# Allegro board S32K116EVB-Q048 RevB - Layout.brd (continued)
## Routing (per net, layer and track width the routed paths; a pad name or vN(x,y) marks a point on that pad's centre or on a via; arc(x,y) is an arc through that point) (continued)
P3V3: length 33.7
  TOP w0.381: 41.49,32.42 TS5.1 ; TS5.1 43.4,33.5 ; TS5.1 45.3,32.42 ; TS5.1 43.4,31.34
  TOP w0.508: C557.1 v1(44.67,9.56) ; 42.32,30.53 C24.1 44.23,30.53
  TOP w0.635: C557.1 TP510.1 45.55,5.25 J3.7
  TOP w0.762: 39.9,33.91 R737.2 41.43,33.91 ; 42.44,34.54 C548.1 ; C548.1 42.95,34.04 ; C548.1 42.95,35.05 ; J10.1 39.57,30.52 ; J10.1 40.52,29.57 ; J10.1 38.61,29.57 ; J10.1 39.57,29.42 40.54,28.45
  L3_INT_1 w0.508: J10.1 39.57,30.52 ; J10.1 40.3,30.3 ; J10.1 38.83,30.3 ; J10.1 40.3,28.83 ; J10.1 39.57,28.61 ; J10.1 38.61,29.57 ; J10.1 38.83,28.83 ; J10.1 40.52,29.57 ; 44.73,5.12 J3.7 ; J3.7 46.42,5.86 ; J3.7 44.94,5.86 ; J3.7 45.68,6.07 ; J3.7 44.94,4.38
  vias: v1(41.62,27.72) v1(41.74,30.52) v1(41.74,29.12) v1(44.92,30.52) v1(44.92,28.61)
P3V3_SDA: length 33.9
  TOP w0.178: v1(33.64,39.64) 33.64,39.65 U9.5
  TOP w0.203: U1.1 9.04,50.33 ; U1.1 8.46,50.04 ; U1.1 8.46,50.62 ; C18.1 30.44,35.34 ; 30.5,36.03 C19.1 ; C19.1 31.01,35.52 ; C19.1 31.01,36.54 ; 31.02,36.6 R52.1 30.51,37.11 ; R77.1 20.43,28.74 C26.1 ; 9.7,50.55 C3.1 9.19,51.06 ; R607.1 v1(8.72,53.38)
  TOP w0.254: U8.7 16.58,40.88 16.01,40.88 15.64,40.52 ; U10.1 v1(27.41,38.62) ; J12.1 18.73,28.86 18.85,28.74 C26.1 ; v1(27.83,41.93) 27.86,41.93 28.13,41.66 U7.1 ; R1.2 v1(9.42,54.36) ; U8.11 v1(16.65,37.9) ; U4.1 28.54,45.51 v1(28.2,45.85) ; U2.1 v1(27.21,48.5) ; v1(30.04,45.2) 30.3,45.46 R15.1 ; U8.1 v1(19.51,43.09)
  TOP w0.381: R3.1 9.8,51.16 C3.1
  TOP w0.508: R60.1 v1(11.75,37.33) ; R42.1 R39.2 37.61,41.46 C10.1 v1(37.61,42.64) ; R30.1 30.95,42.34 30.92,42.37 30.92,42.95 v1(30.91,42.95) ; R12.1 26.29,45.87 v1(25.42,46.74) ; v1(12.41,39.29) R627.2 13.17,40.17 13.52,40.52 C12.1 15.64,40.52
  TOP w0.635: C6.1 17.76,44.83 C7.1 18.65,43.95 v1(19.51,43.09)
  BOTTOM w0.635: 17.32,28.13 J12.1
  vias: v1(8.85,50.86) v1(30.38,36.71)
P5V0: length 168
  TOP w0.508: C558.1 v1(48.09,7.98) ; R729.2 v1(5.74,56.01)
  TOP w0.584: R95.2 R96.2 R97.2
  TOP w0.635: R95.2 109.18,18.83 106.64,21.37 106.64,25.44 v1(105.5,26.58) ; v1(44.16,14.52) 45.17,13.5 R56.1 ; R624.1 35.78,36.11 34.76,35.09 C22.1 ; C22.1 C550.1 ; C22.1 R169.1 32.65,33.69 32.22,33.26 C21.1 28.46,33.26 TP527.1
  L3_INT_1 w0.381: 47.27,5.12 J3.9 ; J3.9 47.48,4.38 ; J3.9 48.96,5.86 ; J3.9 47.48,5.86 ; J3.9 49.17,5.12 ; J3.9 48.96,4.38 ; J3.9 48.22,6.07
  BOTTOM w0.508: 42.13,32.8 49.39,32.8 56.12,26.07 66.15,26.07 67.48,27.39 70.93,27.39 71.95,26.38 77.36,26.38 78.99,28.02 80.36,28.02 81.32,28.97 103.11,28.97 v1(105.5,26.58) ; v1(5.74,56.01) 5.74,55.63 3.83,53.72 3.83,52.32 2.74,51.23 2.74,49.48 6.37,45.85 6.37,35.64 8.89,33.12 8.89,28.09 10.56,26.42 15.95,26.42 16.91,27.38 18.9,27.38 22.4,30.88 23.87,30.88 J107.2
  BOTTOM w0.635: J10.3 35.44,29.57 ; J10.3 34.49,30.52 ; J10.3 34.49,28.61 ; J10.3 33.53,29.57 ; 24.28,29.51 J107.2 ; J107.2 25.24,30.47 ; J107.2 25.24,28.56 ; J107.2 26.19,29.51 ; 28.41,31.97 TP527.1 ; TP527.1 27.06,33.31 ; TP527.1 29.76,33.31
  vias: v1(40.6,25.74) v1(41.49,25.74) v1(42.48,25.72)
P5V0_SDA_USB_CONN_VBUS: length 5.6
  TOP w0.152: 8.02,40.99 D17.2 7.4,41.45
  TOP w0.356: 5.64,42.72 J7.1
  TOP w0.381: L1.1 8.02,40.99
  TOP w0.635: 5.64,42.72 6.92,41.45 7.4,41.45
P5V_SBC: length 93.7
  TOP w0.203: R620.1 41.75,22.77 ; R620.1 41.24,22.26 ; R620.1 40.73,22.77 ; R619.1 36.92,25.44 ; R619.1 37.43,24.93 ; R619.1 36.41,24.93 ; v1(36.92,19.6) 37.3,19.22 R621.1 U34.1 ; 41.87,22.39 R562.1 ; R562.1 42.89,22.39 ; R562.1 42.38,21.88 ; 37.62,24.68 U26.1 ; 42.89,22.64 43.01,22.52 U32.1 ; U33.1 v1(47.97,22.52) R617.1 ; 42,24.55 R572.1
  TOP w0.305: U19.5 22.77,17.74 C547.1
  TOP w0.381: 42.63,21.12 42.63,19.34 R576.1 v1(42.13,18.08) 41.77,17.73 R622.1
  TOP w0.508: v1(12.53,21.63) 12.53,21.63 11.9,21.63 11.61,21.34 R536.1 ; v1(51.45,21.36) 51.59,21.5 v1(52.12,21.5) 52.54,21.08 R618.1 52.91,20.61 53.41,21.12 TP525.1 53.05,21.8 R571.1 TS8.1 ; v1(20.94,14.16) 21.07,14.16 21.09,14.14 C27.1 21.98,14.69 23.18,15.89 23.18,16.68 22.82,17.03 C547.1
  TOP w0.635: R594.1 R535.1 24.16,21.45 v1(25.36,22.66) 25.36,27.1 J107.1
  L3_INT_1 w0.635: v1(25.36,22.66) 22.83,22.66 18.83,26.66 18.55,26.66 18.54,26.67 14.04,26.67 12.53,25.17 v1(12.53,21.63) 14.08,21.63 14.49,22.03 16.87,22.03 17.46,21.45 17.46,14.87 18.17,14.16 v1(20.94,14.16)
  BOTTOM w0.254: v1(42.13,18.08) 41.61,17.56 37.55,17.56 36.93,18.19 36.93,19.6 v1(36.92,19.6)
  BOTTOM w0.508: 27.78,28.56 J107.1 ; J107.1 26.82,28.56 ; J107.1 28.73,30.47 ; J107.1 28.73,28.56 ; J107.1 28.73,29.51 ; J107.1 27.78,30.47 ; J107.1 26.82,30.47
  vias: v1(34.58,24.56) v1(35.57,25.36) v1(35.65,24.14) v1(40.22,22.64) v1(43.01,21.76)
P5V_SDA: length 8.6
  TOP w0.254: U8.6 16.74,41.43 v1(16.62,41.43)
  TOP w0.381: R14.1 22.56,45.36 v1(22.02,45.89)
  TOP w0.508: C15.1 7.5,37.47 7.18,37.79 v1(7.18,38.88) L1.2 ; R57.1 v1(26.57,37.38) ; R70.1 v1(8.14,31.06) ; U11.1 v1(8.08,31.93) ; C25.1 v1(8.15,29.82) ; C11.1 v1(9.35,38.48)
P5V_SDA_PSW: length 26
  TOP w0.584: U11.6 8.08,34.91 v1(6.95,33.78)
  BOTTOM w0.584: J107.3 19.84,26.66 17.3,26.66 16.16,25.53 10.18,25.53 6.95,28.76 v1(6.95,33.78)
VBATT: length 38.6
  TOP w0.508: 25.23,8.42 C555.1 25.74,7.91 ; 54.89,5.12 J3.15 ; J3.15 56.79,5.12 ; J3.15 55.84,6.07 ; J3.15 55.84,4.17 ; TP522.1 25.87,13.32 ; TP522.1 27.22,11.98 ; TP522.1 25.87,10.63 ; TP522.1 24.52,11.98 ; 55.27,8.29 TP507.1 ; TP507.1 56.41,8.29 ; TP507.1 55.84,8.87 ; TP507.1 55.84,7.72 ; 25.74,10.07 C544.1 25.23,9.56 ; 38.06,4.17 J3.1 ; J3.1 37.11,5.12 ; J3.1 38.06,6.07 ; J3.1 39.01,5.12
  TOP w0.635: R606.2 v1(9.61,18.2)
  TOP w0.762: 28.75,10.73 D9.A ; D9.A 28.75,13.22 ; D9.A 27.86,11.98 ; D9.A 29.64,11.98
  TOP w1.27: J16.1 23.2,9.88 ; J16.1 22.29,7.96 ; J16.1 22.29,11.8
  L3_INT_1 w0.254: 24.52,11.98 TP522.1
  L3_INT_1 w0.635: J11.2 3.84,33.27 ; J11.2 2.82,32.26 ; J11.2 2.82,34.29 ; J11.2 1.81,33.27
  L3_INT_1 w1.27: 21.37,9.88 J16.1 ; J16.1 22.29,11.8 ; J16.1 22.29,7.96 ; J16.1 23.2,9.88
  vias: v2(23.12,6.4) v2(23.93,7.2) v2(24.41,10.41) v2(24.41,8.51) v2(24.92,5.97)
VDD: length 82.1
  TOP w0.254: v1(9.49,45.93) 9.18,45.63 Q10.4
  TOP w0.33: 78.64,45.59 R573.1 ; R573.1 78.64,46.61 ; R573.1 78.13,46.1 ; J15.1 47.12,30.76 ; J15.1 48.07,29.81 ; J15.1 46.16,29.81 ; TS1.1 44.79,43.35 ; TS1.1 44.79,39.53 ; TS1.1 43.71,41.44 ; TS1.1 45.87,41.44 ; C553.1 83.91,41.31 ; C553.1 83.91,40.3 ; C553.1 83.4,40.81 ; 81.99,40.13 R121.1 ; R121.1 82.5,39.62 ; R121.1 83.01,40.13 ; TPAD99.1 47.14,32.77 ; TPAD99.1 46,32.77 ; TPAD99.1 46.57,33.34 ; TPAD99.1 46.57,32.2 ; 51.52,34.01 TP511.1 ; TP511.1 52.1,34.58 ; TP511.1 51.52,35.15 ; TP511.1 50.95,34.58 ; 41.79,36.83 TP9.1 ; TP9.1 43.13,38.18 ; TP9.1 44.48,36.83 ; 47.95,42.8 TP4.1 ; TP4.1 50.65,42.8 ; TP4.1 49.3,41.45 ; TP4.1 49.3,44.15 ; 78.32,48.93 R623.1 78.83,48.42 ; 49.49,34.33 R593.1 50.13,33.57 ; 40.45,38.32 SH1.2 41.13,37.72 ; 78.83,50.46 R574.1 78.32,49.95 ; 47.33,32.04 R117.1 47.97,31.28
  TOP w0.381: R733.1 v1(12.22,46.1)
  TOP w0.508: SW3.2 v1(113.97,27.21) ; v1(45.68,14.92) 45.68,16.29 R604.1 ; SW2.4 v1(113.97,30.97) ; SW3.4 v1(113.97,19.46) ; SW2.2 v1(113.97,38.79)
  TOP w0.635: 83.77,42.63 J14.1 85.1,43.36
  L3_INT_1 w0.508: 41.79,36.83 TP9.1 ; TP9.1 43.13,35.48 ; TP9.1 42.12,35.81 ; TP9.1 42.12,37.85 ; TP9.1 44.15,35.81 ; TP9.1 44.15,37.85 ; TP9.1 43.13,38.18 ; TP9.1 44.48,36.83 ; J10.2 37.76,28.83 ; J10.2 36.07,29.57 ; J10.2 36.29,30.3 ; J10.2 37.76,30.3 ; J10.2 36.29,28.83 ; J10.2 37.03,28.61 ; J10.2 37.03,30.52
  BOTTOM w0.508: v1(45.68,14.92) 45.68,14.67 40.68,9.66 37.93,9.66 34.69,6.42 34.69,3.68 v1(35.98,2.4)
  vias: v1(64.73,1.18) v1(67.27,1.21) v1(69.65,1.18) v1(71.84,1.18) v2(40.86,40.93) v2(40.92,39.5) v2(42.25,39.54) v2(42.38,40.93) v2(43.4,39.54) v2(79.91,55.75) v2(79.91,54.23) v2(79.91,52.7) v2(81.05,55.75) v2(81.05,54.23)
VDD_MCU: length 77.9
  TOP w0.254: 79.68,29.19 U36.31 U37.21 ; U37.3 69.83,29.69 U36.5
  TOP w0.305: U36.5 68.2,29.69 67.99,29.9
  TOP w0.381: 79.68,29.19 80.32,29.19 80.62,29.49 C129.1 81.1,29.49 v1(81.58,29.97) 82.04,30.43 C143.1
  TOP w0.508: 67.99,29.9 66.85,31.04 C140.1 C144.1 66.04,33.2 v1(65.51,33.73)
  TOP w0.584: 50.13,32.04 R117.2 49.49,31.28 ; R300.1 63.84,41.95 ; R300.1 63.84,40.42 ; R300.1 63.21,41.19 ; TS2.1 61.68,38.39 ; TS2.1 59.78,39.47 ; TS2.1 57.87,38.39 ; TS2.1 59.78,37.31 ; 59.46,40.07 D59.1 ; D59.1 58.63,40.89 ; D59.1 60.29,40.89 ; 63.46,42.71 L512.2 ; L512.2 63.97,43.22 ; L512.2 63.97,42.2 ; 47.12,26.31 J15.2 ; J15.2 46.16,27.27 ; J15.2 47.12,28.22 ; J15.2 48.07,27.27
  L3_INT_1 w0.508: v1(64.61,44.23) 64.61,42.83 66.03,41.41 66.03,34.25 v1(65.51,33.73) ; v1(81.58,29.97) 81.58,33.32 83.02,34.76 v1(83.02,36.23) 83.02,38.03 81.38,39.67 81.38,41.68 v1(81.33,41.73)
  BOTTOM w0.508: v1(81.33,41.73) 80.53,40.93 71.66,40.93 70.36,42.24 67.21,42.24 65.21,44.23 v1(64.61,44.23) 64.58,44.26 v1(63.44,44.26)
VDD_PERH: length 188.1
  TOP w0.203: v1(48.86,24.17) 49.03,24.17 49.47,23.73 U33.8 ; U32.8 43.88,23.69 v1(43.41,24.17) ; U34.8 38.8,20 38.7,20.1 38.44,20.1 38.27,19.93 v1(38.27,19.85) ; U26.8 38.55,25.97 38.32,26.2 v1(37.55,26.2) ; R612.1 43.01,26.45 v1(43.27,26.71) R616.1
  TOP w0.381: R615.1 v1(37.44,21.63) ; R614.1 41.65,21.63 v1(41.93,21.35)
  TOP w0.508: R611.1 51.9,26.48 51.55,26.84 49.51,26.84 47.84,25.17 R610.1 ; R610.1 47.25,24.93 46.9,25.28 R609.1 ; R610.1 47.84,24.55 48.22,24.17 v1(48.86,24.17) ; R674.1 v1(105.37,52.54)
  TOP w0.635: v1(34.76,22.9) 34.25,22.39 R538.1 R530.1 R570.1 35.08,26.96 TP541.1 35.84,27.22 R613.1 36.41,26.45 36.66,26.2 v1(37.55,26.2) ; 53.56,12.8 TS6.1 ; TS6.1 51.65,13.88 ; TS6.1 53.56,14.96 ; TS6.1 55.46,13.88 ; TP526.1 48.09,36.77 v1(48.09,34.71) 48.09,33.97 47.97,33.85 R593.2 ; v1(31.93,51.64) 31.47,51.18 30.12,51.18
  TOP w0.762: C554.1 v2(33.74,7.58) 33.74,7.66 C556.1 35.6,8.55 36.28,7.86 39.01,7.86 39.77,7.1 39.77,5.95 J3.3
  L3_INT_1 w0.635: v1(48.86,24.17) 48.59,24.43 48.59,34.21 v1(48.09,34.71) 46.58,36.22 46.58,41.88 38.4,50.06 35.81,50.06 34.77,51.1 32.46,51.1 32.24,51.32 32.24,51.32 v1(31.93,51.64) ; v2(33.74,7.58) 36.41,10.25 36.41,14.41 35.37,15.46 34.38,15.46 32.98,16.85 32.98,21.5 34.38,22.9 v1(34.76,22.9) ; v1(55.33,20.99) 54.67,20.33 54.67,16.19 v1(55.84,15.02) v1(55.84,14.01) v1(55.84,12.99) 55.84,8.9 58.01,6.73 67.64,6.73 68.49,7.58 82.41,7.58 83.4,6.59 v2(83.4,5.25) v2(83.4,4.36)
  BOTTOM w0.508: 39.2,20.99 38.82,21.37 37.69,21.37 v1(37.44,21.63) 36.17,22.9 v1(34.76,22.9) ; 39.2,20.99 39.2,20.1 38.95,19.85 v1(38.27,19.85) ; 39.2,20.99 39.56,21.35 41.93,21.35 v1(41.93,21.35) ; v1(43.41,24.17) 43.41,26.57 v1(43.27,26.71)
  BOTTOM w0.635: v1(55.33,20.99) 52.16,24.17 v1(48.86,24.17) v1(43.41,24.17) 42.25,24.17
  BOTTOM w0.762: v1(37.55,26.2) 38.98,24.78 41.47,24.78 42.08,24.17 42.25,24.17
VDDA_MCU: length 64.1
  TOP w0.254: U36.6 66.9,29.19 66.63,29.46 66.43,29.46
  TOP w0.381: 66.43,29.46 C543.1 66.06,29.79 65.68,30.17 62.15,30.17 C542.1 61.82,29.29 v1(61.24,28.7)
  TOP w0.508: C543.1 65.98,29.38 v1(65.98,28.73) ; R569.1 TP545.1 v1(53.24,37.72)
  TOP w0.584: R300.2 65.37,41.95 ; R300.2 65.37,40.42 ; R300.2 66,41.19 ; 64.99,42.2 L512.1 ; L512.1 64.99,43.22 ; L512.1 65.49,42.71 ; 66.57,41.19 D60.1 ; D60.1 67.4,40.36 ; D60.1 68.22,41.19
  L3_INT_1 w0.508: v1(53.24,37.72) 53.49,37.46 v1(53.49,32) ; v1(60.6,41.91) 59.84,41.15 59.84,30.1 v1(61.24,28.7)
  BOTTOM w0.508: v1(53.49,32) 54.13,31.37 60.09,31.37 62.73,28.73 v1(65.98,28.73) ; v1(70.93,40.02) 69.08,40.02 v1(68.92,40.17) 62.34,40.17 v1(60.6,41.91)
ADC_POT: length 66.8
  TOP w0.16: C549.1 R597.2 TP528.1 105.24,48.2 v1(105.45,47.99) ; v1(84.86,32.51) 85.48,33.14 85.48,38.22 87.53,40.26 v1(87.53,41.27) ; v1(84.48,27.3) 84.5,27.3 84.5,27.28 84.84,27.28 85,27.12 85,26.86 R750.1 ; R711.2 80.29,39.88 v1(79.93,40.23) 79.7,40.23 79.18,40.75 R670.1 ; R727.1 v1(83.15,19.37)
  L3_INT_1 w0.165: v1(84.86,32.51) 83.84,32.51 83.08,31.75 83.08,29.82 82.83,29.57 82.83,28.96 v1(84.48,27.3) 84.5,27.3 84.5,27.28 84.48,27.28 82.61,25.41 82.61,19.9 v1(83.15,19.37)
  BOTTOM w0.16: v1(105.45,47.99) 105.03,48.41 89.2,48.41 88.29,47.5 88.29,42.03 v1(87.53,41.27) 84.84,41.27 83.81,40.23 v1(79.93,40.23)
AREF: length 27.8
  TOP w0.508: R569.2 v1(52.35,41.34)
  L3_INT_1 w0.508: v1(52.35,41.34) 52.41,41.34 53.11,42.04 53.11,45.72 50.19,48.64 42.06,48.64 39.14,51.56 36.45,51.56 34.63,53.38 J2.8
BTN0: length 31.2
  TOP w0.16: R659.2 v1(84.92,34.58) ; C16.1 109.47,31.03 R596.2 TP530.1 106.9,29.32 106.31,28.74 92.54,28.74 91.78,29.5 v1(91.78,31.41)
  BOTTOM w0.16: v1(84.92,34.58) 88.1,31.41 v1(91.78,31.41)
BTN1: length 46.9
  TOP w0.16: R660.2 v1(73.39,16.22) ; C28.1 109.55,27.34 R595.2 TP529.1 106.01,28.11 89.5,28.11 88.31,26.92 88.31,19.96 86.8,18.45 v1(84.17,18.45)
  BOTTOM w0.16: v1(84.17,18.45) 82.26,18.45 81.37,17.56 76.29,17.56 74.94,16.22 v1(73.39,16.22)
CAN_HI: length 22.8
  TOP w0.16: v1(14.44,16.36) 14.82,16.74 U19.18 ; R92.1 2.87,23.28 J13.1 ; R92.1 v1(8.85,23.28) ; R92.1 TP504.1
  L3_INT_1 w0.165: v1(8.85,23.28) 8.85,22.33 10.39,20.79 15.26,20.79 15.58,20.48 15.58,20 14.44,18.86 14.44,18.44 14.43,18.43 14.43,18.05 14.44,18.04 v1(14.44,16.36)
CAN_LO: length 21.2
  TOP w0.16: J13.2 4.53,18.98 4.53,15.02 6.18,13.37 R98.2 7.33,14.26 10.31,17.24 TP503.1 U19.17
EXTAL: length 6.6
  TOP w0.16: Y3.1 57.23,28.25 57.8,28.82 C126.1 59.17,28.82 R91.1 R88.1
JTAG_TCLK/SWD_CLK: length 102.5
  TOP w0.127: U37.30 73.28,31.63 72.92,31.99 72.74,31.99 72.52,32.22 72.42,32.22 72.41,32.24
  TOP w0.16: R626.1 v1(28.03,35.09) ; v1(80.34,43.18) 79.93,43.18 79.78,43.33 R575.1 80.97,43.97 81.63,44.63 J14.4 ; 72.41,32.24 72.28,32.36 U36.46 72.28,34.75 71.38,35.65 71.38,37.93 73.55,40.1 73.55,46.06 72.96,46.65 TP536.1 68.24,48.73 61.73,48.73 60.67,47.66 v1(60.67,44.23)
  L3_INT_1 w0.165: v1(51.08,39.62) 51.08,36.96 v1(50.95,36.83)
  BOTTOM w0.16: v1(51.08,39.62) 51.54,39.17 54.44,39.17 59.51,44.23 v1(60.67,44.23) 60.68,44.22 62.53,44.22 63.08,44.77 65.7,44.77 67.26,43.21 70.51,43.21 71.12,42.6 75.46,42.6 76.27,41.78 79.82,41.78 80.34,42.3 v1(80.34,43.18) ; v1(50.95,36.83) 50.32,36.83 49.68,36.2 46.23,36.2 43.65,38.77 38.67,38.77 36.13,36.23 34.25,36.23 33.11,35.09 v1(28.03,35.09)
JTAG_TDI: length 15
  TOP w0.16: R120.2 v1(78.1,47.73) ; v1(75.06,47.8) 75.06,47.47 73.99,46.41 73.99,45.57 74.26,45.3 TP538.1 74.26,43.26 73.92,42.93 73.92,39.63 R632.1
  BOTTOM w0.16: v1(75.06,47.8) 75.23,47.97 77.86,47.97 v1(78.1,47.73)
JTAG_TDO: length 15.3
  TOP w0.16: v1(80.21,45.59) 79.65,45.04 R119.2 ; R645.1 73.65,38.49 74.26,39.09 74.26,42.58 74.85,43.18 74.85,46.18 v1(74.76,46.27)
  BOTTOM w0.16: v1(80.21,45.59) 75.44,45.59 v1(74.76,46.27)
JTAG_TMS/SWD_DIO: length 73.9
  TOP w0.16: U37.32 72.28,31.59 72.12,31.75 71.42,31.75 71.28,31.89 U36.48 71.28,34.19 70.69,34.78 70.69,38.56 72.86,40.73 72.86,44.49 TP535.1 72.07,44.74 v1(71.64,44.31) ; R625.1 34.69,46.59 v1(34.94,46.34) ; v1(78.76,42.93) 79.26,42.43 80.43,42.43 81.35,43.36 J14.2 R121.2
  BOTTOM w0.16: v1(34.94,46.34) 35.37,45.91 40.07,45.91 45.34,40.64 55.22,40.64 59.35,44.77 62.47,44.77 62.81,45.11 70.84,45.11 v1(71.64,44.31) 72.9,43.05 75.72,43.05 76.62,42.15 77.73,42.15 78.51,42.93 v1(78.76,42.93)
LEDRGB_BLUE: length 16.2
  TOP w0.16: Q8.3 97.08,7.32 98.46,7.32 100.32,9.18 106.39,9.18 108.09,7.48 TP28.1 D11.C3
LEDRGB_GREEN: length 19.9
  TOP w0.16: D11.C2 TP29.1 110.52,6.64 108.29,6.64 106.26,8.67 100.44,8.67 98.01,6.24 98.01,5.5 97.5,4.99 Q7.3
LEDRGB_RED: length 21.6
  TOP w0.16: Q6.3 97.5,2.71 98.51,1.69 107.67,1.69 TP30.1 D11.C1
LIN: length 37.1
  TOP w0.406: J11.1 C17.1 5.51,26.03 TP18.1 8.04,25.43 8.72,24.75 R80.1 R171.1 12.28,25.31 10.88,26.71 TS4.1 11.36,27.94 16.02,27.94 16.91,27.05 19.49,27.05 21.11,25.43 U21.6
LIN_RX: length 84.8
  TOP w0.16: R538.2 31.84,22.9 31.44,22.9 31.44,22.89 v1(31.2,22.89) U21.1 ; R664.1 72.12,16.65 v1(72.22,16.55) 72.73,16.04 TP519.1 ; R679.2 76.35,41.23 76.35,43.08 v1(76.68,43.41)
  L3_INT_1 w0.165: v1(76.68,43.41) 75.06,43.41 73.69,42.04 73.69,32.51 71.83,30.66 71.83,20.7 72.59,19.94 72.59,16.91 v1(72.22,16.55)
  BOTTOM w0.16: v1(31.2,22.89) 31.72,23.41 37.14,23.41 38.62,21.93 42.08,21.93 43.82,20.19 51.4,20.19 51.84,19.75 56.23,19.75 59.34,16.64 62.2,16.64 62.27,16.7 68.79,16.7 69.41,16.09 71.76,16.09 v1(72.22,16.55)
LIN_SLP: length 85.3
  TOP w0.16: v1(26.38,24.16) U21.2 31.18,24.16 31.43,23.91 R530.2 32.35,25.06 R661.1 ; v1(48.35,17.82) 48.86,17.82 49.87,16.8 TP521.1 51.84,17.5 51.84,19.05 52.35,19.56 56.16,19.56 57.17,20.57 58.06,20.57 v1(58.25,20.37) ; R672.1 83.84,25.63 83.84,25.12 84.05,24.92 84.56,24.92 85.29,24.18 85.49,24.18 85.77,23.89 85.77,23.24 v1(85.31,22.77)
  L3_INT_1 w0.165: v1(24.73,18.2) 24.73,19.6 26.07,20.94 26.07,23.85 v1(26.38,24.16)
  BOTTOM w0.16: v1(58.25,20.37) 58.58,20.7 73.51,20.7 74.11,21.3 75.05,21.3 76.13,22.39 84.92,22.39 v1(85.31,22.77) ; v1(48.35,17.82) 47.03,16.5 36.84,16.5 35.14,18.2 v1(24.73,18.2)
LIN_TX: length 85.4
  TOP w0.16: R665.1 70.98,16.57 v1(70.95,16.55) 70.98,16.52 70.98,15.3 TP520.1 ; R570.2 31.86,26.96 31.6,26.7 v1(31.2,26.7) U21.4 ; v1(76.93,42.61) 76.92,42.61 76.92,41.8 R680.2
  L3_INT_1 w0.165: v1(70.95,16.55) 71.7,15.81 72.4,15.81 72.93,16.34 72.93,20.34 72.24,21.03 72.24,26.11 73.13,27 73.13,31.11 74.03,32.02 74.03,41.85 74.78,42.6 76.91,42.6 76.92,42.61 v1(76.93,42.61)
  BOTTOM w0.16: v1(70.95,16.55) 70.28,17.22 61.98,17.22 61.73,16.98 59.63,16.98 56.52,20.09 55.35,20.09 51.89,23.55 42.73,23.55 42.66,23.48 38.62,23.48 35.4,26.7 v1(31.2,26.7)
LVLRST_EN: length 5.6
  TOP w0.16: U1.5 6.46,50.33 6.25,50.55 6.25,51.82 6.5,52.07 6.5,53.88 6.98,54.36 R1.1
MIC2005_CSLEW: length 1.8
  TOP w0.16: U11.5 C15.2
POWER_EN: length 15.7
  TOP w0.16: v1(20.95,42.96) 20.95,42.91 U8.31 ; R69.1 v1(12.64,32.91)
  BOTTOM w0.16: v1(12.64,32.91) 12.64,34.08 15.65,37.09 15.65,38.42 16.73,39.5 17.25,39.5 20.71,42.96 v1(20.95,42.96)
PTA0: length 128.8
  TOP w0.16: v1(26.82,51.05) 26.82,50.56 27.22,50.16 R718.1 ; v1(76.78,47.02) 76.78,44.07 77.39,43.46 77.39,42.14 78.57,40.96 78.57,39.48 79.11,38.95 R673.1 ; v1(62.61,10.44) 62.08,9.91 R742.1
  L3_INT_1 w0.165: v1(82.23,11.56) 82.23,29.46 82.73,29.97 82.73,32.19 83.57,33.02 85.21,33.02 85.39,33.19 85.39,38.4 81.37,42.42 80.45,42.42 79.65,43.21 79.65,45.21 77.85,47.02 v1(76.78,47.02)
  BOTTOM w0.16: v1(26.82,51.05) 27.91,52.15 32.26,52.15 32.69,51.71 53.31,51.71 54.99,50.04 59.27,50.04 61.33,47.98 68.67,47.98 69.64,47.01 74.12,47.01 74.4,47.29 76.51,47.29 v1(76.78,47.02) ; v1(82.23,11.56) 81.01,10.34 71.78,10.34 70.76,11.36 69.07,11.36 68.15,10.44 v1(62.61,10.44)
PTA0_MCU: length 10.6
  TOP w0.16: R670.2 79.65,39.19 79.65,37.62 R673.2 76.28,34.24 U36.38 76.28,32.34 76.12,32.18 75.79,32.18 75.28,31.67 U37.26
PTA1: length 122.1
  TOP w0.16: v1(86.79,50.04) 87.3,49.53 87.3,42.29 86.55,41.54 86.55,40.4 84.51,38.35 83.36,38.35 81.08,36.07 R741.1 79.37,35.23 v1(79.37,34.67) ; v1(34.69,50.16) 34.69,50.93 34.44,51.18 33.81,51.18 ; v1(73.51,12.04) 73.28,11.81 R743.1
  L3_INT_1 w0.165: v1(73.51,12.04) 73.2,12.34 66.29,12.34 65.68,12.95 65.68,18.54 67.71,20.57 67.71,34.04 v1(68.1,34.42)
  BOTTOM w0.16: v1(68.1,34.42) 68.35,34.67 v1(79.37,34.67) ; v1(86.79,50.04) 81.94,50.04 78.38,46.48 76.55,46.48 76.21,46.83 74.46,46.83 74.24,46.6 69.08,46.6 68.35,47.34 61.11,47.34 58.96,49.48 54.43,49.48 53.11,50.8 35.33,50.8 v1(34.69,50.16)
PTA1_MCU: length 8.1
  TOP w0.16: R741.2 79.3,36.17 78.84,36.17 76.78,34.11 U36.37 76.78,32.2 76.44,31.86 75.94,31.86 75.78,31.7 U37.25
PTA2: length 26
  TOP w0.16: U37.24 76.83,30.69 76.92,30.78 76.92,31.26 77.36,31.7 U36.36 78.94,31.7 80.07,32.83 80.07,34.32 v1(80.29,34.54) ; v1(73.3,47.62) 73.68,48.01 R675.1
  L3_INT_1 w0.165: v1(73.3,47.62) 73.94,48.27 75.25,48.27 75.72,47.8 75.72,45.09 77.75,43.05 77.75,40.87 79.91,38.71 79.91,34.92 v1(80.29,34.54)
PTA3: length 29
  TOP w0.16: R676.1 v1(72.16,47.62) ; U37.23 76.85,30.19 77.23,30.58 77.23,30.97 77.45,31.2 U36.35 78.95,31.2 81.47,33.72 81.47,34.5 v1(81.43,34.54)
  L3_INT_1 w0.165: v1(72.16,47.62) 73.14,48.61 75.39,48.61 76.1,47.9 76.1,45.19 78.09,43.2 78.09,41.01 80.25,38.85 80.25,35.73 v1(81.43,34.54)
PTA7: length 45.9
  TOP w0.16: R749.2 R751.2 ; R749.2 59.1,8.89 59.51,9.3 59.51,12.12 60.79,13.4 v1(60.79,17.56) ; R749.2 58.93,7.95 60.92,5.95 J4.1 ; R671.1 v1(81.55,27.29)
  L3_INT_1 w0.165: v1(81.11,18.33) 81.11,25.08 81.86,25.83 81.86,26.98 v1(81.55,27.29)
  BOTTOM w0.16: v1(81.11,18.33) 80.99,18.2 61.43,18.2 v1(60.79,17.56)
PTA7_MCU: length 11.3
  TOP w0.16: R671.2 82.26,26.25 R672.2 ; R671.2 83.3,27.65 83.13,27.82 80.19,27.82 79.83,28.18 78.24,28.18 U36.29 76.48,28.19 U37.19 ; R671.2 83.54,27.05 83.77,27.05 83.96,26.86 83.98,26.86 R750.2 84.35,26.23 84.5,26.08 R747.2
PTA10_MCU: length 6.4
  TOP w0.127: 73.42,32.26 73.46,32.22 73.52,32.22 73.74,31.99 73.92,31.99 74.28,31.63 U37.28
  TOP w0.16: R645.2 73.65,36.55 73.3,36.2 73.3,34.84 73.28,34.82 U36.44 73.28,32.4 73.42,32.26
PTA11: length 51.4
  TOP w0.16: v1(74.66,38.85) R669.1 ; R751.1 57.73,9.65 v1(54.38,9.65) R752.1
  L3_INT_1 w0.165: v1(74.66,38.85) 74.66,25.92 73.79,25.04 73.79,20.25 74.22,19.81 74.22,15.52 v1(72.86,14.16)
  BOTTOM w0.16: v1(54.38,9.65) 55.16,9.65 57.07,11.56 60.35,11.56 61.05,12.26 65.24,12.26 67.14,14.16 v1(72.86,14.16)
PTA11_MCU: length 9.8
  TOP w0.127: 73.89,32.24 73.91,32.22 74.02,32.22 74.05,32.18 74.48,32.18 74.78,31.89 U37.27
  TOP w0.16: 73.89,32.24 73.78,32.35 U36.43 73.78,36.19 R669.2 75.19,37.6 75.19,39.47 R668.2
PTA12: length 28.5
  TOP w0.16: v1(75.13,50.43) 75.13,50.44 75.54,50.04 75.54,36.85 74.28,35.59 U36.42
  BOTTOM w0.16: v1(75.13,50.43) 74.96,50.6 68.56,50.6 66,53.15 J1.4
PTA13: length 27.1
  TOP w0.16: U36.41 74.78,35.65 75.87,36.74 75.87,51.73 v1(75.56,52.04)
  BOTTOM w0.16: J1.3 69.88,52.04 v1(75.56,52.04)
PTB0: length 85.2
  TOP w0.16: R748.1 v1(84.33,10.03) ; R754.1 34.64,4.78 v1(35.71,5.84) ; R662.1 v1(84.04,24.04)
  L3_INT_1 w0.165: v1(84.04,24.04) 84.43,23.65 84.43,22.66 86.41,20.68 86.41,10.44 86,10.03 v1(84.33,10.03) ; v1(52.95,18.3) 53.8,19.15 53.8,25.33 v1(53.4,25.72)
  BOTTOM w0.16: v1(52.95,18.3) 52.21,17.56 51.07,17.56 42.11,8.61 38.48,8.61 v1(35.71,5.84) ; v1(84.04,24.04) 76.77,24.04 74.71,21.98 73.83,21.98 73.27,21.42 55.79,21.42 53.75,23.46 53.75,25.37 v1(53.4,25.72)
PTB0_MCU: length 8.2
  TOP w0.16: R662.2 R666.2 81.91,25.53 80.57,25.53 79.41,26.69 U36.26 77.42,26.69 77.26,26.85 77.26,27.18 76.75,27.69 U37.18
PTB1: length 60
  TOP w0.16: R749.1 58.44,10.39 58.44,15.93 v1(55.86,18.51) ; R663.1 v1(83.91,22.85) ; v1(42.54,8.28) 42.11,7.85 R753.1
  L3_INT_1 w0.165: v1(56.22,20.74) 55.86,20.38 v1(55.86,18.51)
  BOTTOM w0.16: v1(55.86,18.51) 54.31,18.51 44.08,8.28 v1(42.54,8.28) ; v1(83.91,22.85) 76.11,22.85 74.91,21.64 73.97,21.64 73.41,21.08 56.57,21.08 v1(56.22,20.74)
PTB1_MCU: length 10.5
  TOP w0.16: U37.17 76.73,27.19 76.89,27.03 76.89,26.47 77.17,26.19 U36.25 79.12,26.19 81.11,24.2 81.11,23.3 81.57,22.85 R663.2 82.16,21.78 R667.2 R727.2
PTB2: length 67.8
  TOP w0.16: R642.1 v1(78.6,19.32)
  L3_INT_1 w0.165: v1(57.48,19.86) 57.48,21.76 55.4,23.85 55.4,44.16 49.91,49.64 42.81,49.64 J2.6
  BOTTOM w0.16: v1(57.48,19.86) 57.5,19.87 64.91,19.87 65.37,20.33 72.84,20.33 73.39,19.78 78.14,19.78 v1(78.6,19.32)
PTB2_MCU: length 10.2
  TOP w0.16: R638.2 78.91,18.53 79.34,18.96 79.34,20.33 R642.2 78.6,22.24 76.78,24.06 U36.24 76.78,25.7 76.38,26.1 75.94,26.1 75.78,26.26 U37.16
PTB3: length 66.3
  TOP w0.16: R641.1 v1(77.46,19.32)
  L3_INT_1 w0.165: J2.5 44.7,50.29 50.9,50.29 56.03,45.16 56.03,24.39 58.76,21.65 58.76,18.33 59.56,17.53 v1(59.97,17.53)
  BOTTOM w0.16: v1(59.97,17.53) 60.98,18.54 76.68,18.54 v1(77.46,19.32)
PTB3_MCU: length 9.6
  TOP w0.16: U37.15 75.28,25.95 75.49,25.74 76.03,25.74 76.28,25.49 U36.23 76.28,24 77.46,22.82 R641.2 78.02,20.51 78.02,19.09 R637.2
PTB4: length 55.6
  TOP w0.16: R640.1 v1(69.84,19.19)
  L3_INT_1 w0.165: v1(59.52,18.33) 59.18,18.67 59.18,22.18 56.67,24.69 56.67,45.37 50.99,51.04 46.49,51.04 J2.4
  BOTTOM w0.16: v1(69.84,19.19) 69.52,18.87 60.07,18.87 v1(59.52,18.33)
PTB4_MCU: length 10.3
  TOP w0.127: 72.28,25.54 72.4,25.67 72.52,25.67 72.74,25.9 72.92,25.9 73.28,26.25 U37.11
  TOP w0.16: R636.2 70.37,18.94 70.37,20.54 R640.2 70.05,21.07 71.16,22.19 71.16,22.65 72.28,23.77 U36.15 72.28,25.54
PTB5: length 96.9
  TOP w0.16: v1(68.29,14.77) 68.14,14.92 68.14,18.91 68.69,19.47 R639.1
  L3_INT_1 w0.165: J2.3 44.62,55.45 31.55,55.45 30.37,54.27 30.37,52.7 30.83,52.25 32.74,52.25 33.25,51.74 34.97,51.74 36.05,50.66 38.62,50.66 47.16,42.12 47.16,36.46 49.32,34.3 49.32,24.72 49.78,24.26 49.78,20.65 51.5,18.94 51.5,11.49 v1(51.85,11.14)
  BOTTOM w0.16: v1(68.29,14.77) 62.65,14.77 62.19,14.31 58.05,14.31 54.88,11.14 v1(51.85,11.14)
PTB5_MCU: length 11.1
  TOP w0.127: U37.10 72.78,26.25 72.42,25.9 72.11,25.9
  TOP w0.16: R635.2 68.69,18.96 69.25,19.52 69.25,20.51 R639.2 68.69,21.73 69.76,22.8 70.85,22.8 71.78,23.73 U36.14 71.78,25.67 72,25.9 72.11,25.9
PTB6: length 127.3
  TOP w0.16: v1(44.72,6.77) 44.37,6.43 44.37,4.65 43.14,3.42 J3.6 ; R644.1 v1(64.22,26.78) ; 32.69,51.18 32.51,51.18 v1(31.95,50.63)
  L3_INT_1 w0.165: v1(55.84,17.56) 56.69,18.41 56.69,21.52 54.75,23.46 v1(54.75,36.88) ; v1(31.95,50.63) 31.95,50.62 31.65,50.93 29.28,50.93 27.83,52.38 27.83,53.83 28.73,54.72 30.32,54.72 31.65,56.05 45.83,56.05 47.01,54.86 64.03,54.86 64.55,54.35 64.55,46.03 62.97,44.45 62.97,42.59 64.37,41.19 64.37,36.79 v1(64.02,36.44) 64.02,30.79 63.52,30.29 63.52,27.69 64.22,26.99 v1(64.22,26.78)
  BOTTOM w0.16: v1(44.72,6.77) 44.72,8.44 53.84,17.56 v1(55.84,17.56) ; v1(64.02,36.44) 64.02,36.45 63.39,37.08 54.94,37.08 v1(54.75,36.88)
PTB6_MCU: length 9.9
  TOP w0.16: U37.6 71.28,28.19 70.78,27.69 U36.9 66.94,27.69 R644.2 65.39,26.15 63.36,26.15 62.98,26.53 R84.2
PTB7: length 113.9
  TOP w0.16: J3.8 46.76,3.66 v1(46.76,9.14) ; R643.1 v1(64.3,27.93) ; v1(30.12,55.37) 30.12,52.88 28.92,51.68 28.92,51.18
  L3_INT_1 w0.165: v1(63.97,15.53) 63.36,16.14 63.36,25.15 64.79,26.58 64.79,27.43 v1(64.3,27.93) 64.83,28.45 64.83,41.37 64.37,41.82 64.37,41.85 63.45,42.77 63.45,43.56 63.93,44.04 63.93,44.73 67.09,47.89 67.09,53.83 65.71,55.21 47.16,55.21 45.38,56.98 31.27,56.98 30.12,55.84 v1(30.12,55.37)
  BOTTOM w0.16: v1(46.76,9.14) 46.76,10.01 52.58,15.82 56.79,15.82 57.08,15.53 v1(63.97,15.53)
PTB7_MCU: length 9.7
  TOP w0.16: U37.5 71.27,28.69 70.77,28.19 U36.8 66.29,28.19 R643.2 65.5,27.4 63.38,27.4 R88.2
PTB13: length 5.6
  TOP w0.16: R681.1 81.95,31.53 80.11,29.69 U36.32
PTC1: length 18.9
  TOP w0.16: R739.2 74.6,18.89 74.3,18.59 74.3,14.96 73.7,14.35 v1(73.7,14.34) ; R687.1 63.65,10.92 64.08,11.35 v1(65.78,11.35)
  BOTTOM w0.16: v1(65.78,11.35) 65.78,11.35 66.29,11.35 67.91,12.98 73.17,12.98 73.68,13.5 73.68,14.34 v1(73.7,14.34)
PTC2: length 55.7
  TOP w0.16: R678.1 v1(72.12,19.22)
  L3_INT_1 w0.165: v1(74.22,47.76) 74.22,47.19 73.33,46.3 73.33,33.12 71.39,31.18 71.39,19.95 v1(72.12,19.22)
  BOTTOM w0.16: J2.1 52.98,53.38 55.76,50.59 59.9,50.59 61.94,48.55 73.59,48.55 74.22,47.93 v1(74.22,47.76)
PTC2_MCU: length 9.6
  TOP w0.127: U37.13 74.28,26.25 73.92,25.9 73.74,25.9 73.52,25.67 73.45,25.67 73.28,25.49
  TOP w0.16: 73.28,25.49 U36.17 v1(73.28,23.42) 73.28,22.76 72.12,21.6 R678.2 72.66,20.54 72.66,18.94 R664.2
PTC3: length 51.1
  TOP w0.16: R677.1 v1(70.98,19.32)
  L3_INT_1 w0.165: v1(59.65,19.34) 59.78,19.47 59.78,22.54 57.94,24.38 57.94,45.16 49.72,53.38 J2.2
  BOTTOM w0.16: v1(59.65,19.34) 68.82,19.34 69.13,19.65 70.65,19.65 v1(70.98,19.32)
PTC3_MCU: length 9.9
  TOP w0.127: U37.12 73.78,26.25 73.42,25.9 73.24,25.9 73.02,25.67 72.9,25.67 72.78,25.54
  TOP w0.16: R665.2 71.56,18.99 71.56,20.49 R677.2 70.98,21.5 72.78,23.3 U36.16 72.78,25.54
PTC5_MCU: length 7
  TOP w0.127: U37.29 73.78,31.63 73.42,31.99 73.24,31.99 73.02,32.22 72.95,32.22 72.84,32.33
  TOP w0.16: 72.84,32.33 72.78,32.4 U36.45 72.78,34.7 71.7,35.78 71.7,36.37 72.38,37.05 R632.2
PTC6: length 58.5
  TOP w0.16: J4.2 57.02,6.48 v1(57.02,8.76) ; R683.2 v1(76.82,38.79)
  L3_INT_1 w0.165: v1(57.02,8.76) 62.76,8.76 64.88,10.88 71.08,10.88 71.4,10.57 73.51,10.57 75.75,12.81 75.75,14.47 76.83,15.55 76.83,20.55 77.75,21.46 77.75,33.78 78.43,34.46 78.43,39.09 78.16,39.36 77.4,39.36 v1(76.82,38.79)
PTC6_MCU: length 8
  TOP w0.16: U36.40 75.28,35.53 R683.1 77.25,37.07 77.44,37.26 77.44,38.92 76.82,39.54 R679.1
PTC7: length 54.6
  TOP w0.16: R684.2 v1(77.97,38.9) ; v1(60.12,10.46) 59.89,10.24 59.89,8.36 62.32,5.93 62.32,3.72 J4.4
  L3_INT_1 w0.165: v1(60.12,10.46) 60.98,9.6 62.97,9.6 65.17,11.81 72.52,11.81 72.83,11.49 73.95,11.49 75.41,12.95 75.41,14.61 76.49,15.69 76.49,20.69 77.4,21.61 77.4,33.92 77.97,34.48 v1(77.97,38.9)
PTC7_MCU: length 8
  TOP w0.16: R680.1 77.97,39.54 78.14,39.36 78.16,39.36 78.43,39.09 78.43,39.07 78.55,38.95 78.55,37.66 R684.1 77.87,36.98 77.87,36.42 75.78,34.33 U36.39
PTC8: length 42.5
  TOP w0.16: v1(66.44,9.65) 66.44,9.91 66.28,10.07 R702.1 ; U36.28 79.54,27.69 v1(79.89,27.34) ; R745.1 60.63,10.19 v1(60.98,10.54)
  L3_INT_1 w0.165: v1(79.89,27.34) 79.89,9.1 v1(79.84,9.06)
  BOTTOM w0.16: v1(60.98,10.54) 61.87,9.65 v1(66.44,9.65) 67.84,9.65 69.21,11.02 70.33,11.02 71.37,9.98 78.92,9.98 v1(79.84,9.06)
PTC9: length 35.5
  TOP w0.16: v1(69.59,10.42) 69.59,10.42 69.59,10.41 69.24,10.41 R703.1 ; v1(81.11,26.19) 80.35,26.19 79.35,27.19 U36.27 ; v1(75.21,9.4) 74.92,9.69 R685.1
  L3_INT_1 w0.165: v1(80.99,8.93) 80.99,11.54 80.53,12 80.53,25.61 v1(81.11,26.19)
  BOTTOM w0.16: v1(69.59,10.42) 69.59,10.42 69.84,10.67 70.13,10.67 71.4,9.4 v1(75.21,9.4) 76.06,8.55 80.61,8.55 v1(80.99,8.93)
PTC14: length 30.5
  TOP w0.16: v1(78.13,6.32) 78.13,7.87 77.37,8.64 77.37,11.94 78.64,13.21 78.64,14.58 76.88,16.33 76.88,22.91 75.78,24.01 U36.22
  L3_INT_1 w0.165: J4.7 69.74,6.32 v1(78.13,6.32)
PTC15: length 51.8
  TOP w0.16: U36.21 75.28,23.92 76.5,22.7 76.5,15.95 77.48,14.97 77.48,14.21 76.86,13.59 72.67,13.59 72.31,13.94 71.12,13.94 70.13,12.95 v1(70.13,9.99) 70.13,8.89 71.08,7.94 J4.9 ; v1(85.49,14.49) R746.1
  BOTTOM w0.16: v1(85.49,14.49) 86.26,13.73 86.26,10.01 84.38,8.13 71.99,8.13 v1(70.13,9.99)
PTC16: length 47.6
  TOP w0.16: v1(85.76,31.1) 86.32,31.1 R744.1 ; R686.1 71.14,10.67 71.51,11.03 v1(72.41,11.03) ; v1(76.86,14.86) 75.63,16.09 v1(75.63,20.71) 75.63,23.1 74.78,23.95 U36.20
  L3_INT_1 w0.165: v1(84.99,20.45) 83.44,22 83.44,24.71 85.76,27.03 v1(85.76,31.1)
  BOTTOM w0.16: v1(84.99,20.45) 81.13,20.45 80.86,20.71 v1(75.63,20.71) ; v1(76.86,14.86) 77.32,14.86 78.91,13.27 78.91,11.53 78.1,10.72 73.64,10.72 73.33,11.03 v1(72.41,11.03)
PTD0: length 30.3
  TOP w0.16: v1(62,34.29) 62.73,35.02 66.25,35.02 68.22,33.05 68.22,31.78 68.8,31.2 U36.2
  L3_INT_1 w0.165: J1.5 62.67,52.59 62.67,45.07 62.37,44.77 62.37,36.31 62.59,36.09 62.59,34.88 v1(62,34.29)
PTD1: length 28.7
  TOP w0.16: v1(61.95,35.35) 66.4,35.35 68.63,33.12 68.63,31.93 68.86,31.7 U36.1
  L3_INT_1 w0.165: v1(61.95,35.35) 61.87,35.43 61.52,35.43 61.23,35.73 61.23,44.62 60.92,44.92 J1.6
PTD2: length 57.1
  TOP w0.16: U36.34 78.23,30.7 78.98,30.7 81.93,33.65 81.93,36.41 83.49,37.97 84.61,37.97 86.89,40.26 86.89,41.4 87.65,42.16 87.65,50.04 86.82,50.88 v1(86.26,50.88)
  BOTTOM w0.16: J1.7 62.85,48.91 73.92,48.91 74.52,48.31 79.58,48.31 82.14,50.88 v1(86.26,50.88)
PTD3: length 52.9
  TOP w0.16: v1(84.92,33.57) R696.2
  L3_INT_1 w0.165: v1(84.92,33.57) 83.63,33.57 82.39,32.33 82.39,30.12 81.05,28.78 80.67,28.78 79.4,27.51 79.4,15.51 73.08,9.19 63.95,9.19 62.74,7.98 v1(58.19,7.98)
  BOTTOM w0.16: v1(58.19,7.98) 58.19,4.93 J3.16
PTD3_MCU: length 9.4
  TOP w0.16: R659.1 R696.1 83.07,33.2 80.06,30.19 U36.33 77.33,30.19 76.83,29.69 U37.22
PTD5: length 28.7
  TOP w0.16: R697.2 v1(73.39,19.29) ; v1(67.21,8) 67.21,11.09 65.17,13.13 65.17,19.2 v1(65.81,19.84)
  BOTTOM w0.16: v1(73.39,19.29) 72.7,19.99 68.99,19.99 68.84,19.84 v1(65.81,19.84) ; v1(67.21,8) 69.87,5.33 69.87,3.94 71.08,2.73 J4.10
PTD5_MCU: length 9.4
  TOP w0.127: U37.14 74.78,26.13 74.54,25.9 74.24,25.9 74.02,25.67 73.89,25.67 73.78,25.55
  TOP w0.16: R660.1 73.97,18.98 73.97,20.5 R697.1 73.39,22.14 73.78,22.52 U36.18 73.78,25.55
PTD15: length 30.1
  TOP w0.16: R657.2 v1(64.17,24.24) ; v1(71.98,13.48) 72.92,12.54 72.92,10.64 R693.1
  L3_INT_1 w0.165: v1(61.87,11.79) 63.29,13.21 64.27,13.21 64.43,13.37 64.43,15.34 64.43,15.34 64.43,15.72 64.43,15.73 64.43,23.99 v1(64.17,24.24)
  BOTTOM w0.16: v1(71.98,13.48) 67.1,13.48 65.43,11.81 61.89,11.81 v1(61.87,11.79)
PTD15_MCU: length 10.4
  TOP w0.16: U37.8 71.32,27.19 70.82,26.69 U36.11 69,26.69 66.55,24.24 R657.1 66.03,23.99 65.34,23.3 63.54,23.3 R654.1
PTD16: length 34.7
  TOP w0.16: v1(76.29,11.34) R694.1 ; R656.2 v1(64.27,25.39)
  L3_INT_1 w0.165: v1(64.27,25.39) 65.12,24.54 65.12,13.41 64.41,12.7 63.52,12.7 61.98,11.16 v1(61.61,11.16)
  BOTTOM w0.16: v1(76.29,11.34) 76.07,11.13 73.71,11.13 72.73,12.11 69.08,12.11 67.84,10.87 63.57,10.87 63.29,11.16 v1(61.61,11.16)
PTD16_MCU: length 10.2
  TOP w0.16: U37.7 71.3,27.69 70.8,27.19 U36.10 67.21,27.19 66.03,26.01 R656.1 66.03,25.06 65.82,24.85 63.13,24.85 R653.1
PTE4: length 43.2
  TOP w0.16: v1(61.31,32.42) 61.31,32.44 61.59,32.16 R651.2
  L3_INT_1 w0.165: v1(61.31,32.42) 61.87,31.86 61.87,15.14 v1(61.51,14.77)
  BOTTOM w0.16: v1(61.51,14.77) 61.18,15.1 57.04,15.1 56.65,15.49 53.87,15.49 46.89,8.5 46.89,3.91 J3.10
PTE4_MCU: length 15.9
  TOP w0.16: U37.2 69.83,30.19 U36.4 68.71,30.19 67.49,31.42 67.49,32.77 65.91,34.34 63.95,34.34 63.4,33.78 63.4,33.17 62.61,32.38 R651.1 62,31.12 61.19,31.12 R649.1
PTE5: length 41.9
  TOP w0.16: v1(61.24,33.93) 61.7,33.48 R652.2
  L3_INT_1 w0.165: v1(61.24,33.93) 62.38,32.79 62.38,28.07 63.02,27.43 63.02,14.2 v1(63.08,14.14)
  BOTTOM w0.16: J3.12 51.85,3.66 51.85,9.56 52.82,10.53 55.03,10.53 58.38,13.88 62.83,13.88 v1(63.08,14.14)
PTE5_MCU: length 14.5
  TOP w0.16: U37.1 69.83,30.69 U36.3 68.74,30.69 67.82,31.62 67.82,32.94 66.08,34.68 63.53,34.68 62.86,34.01 R652.1 62.27,32.88 R650.1
PTE8: length 22.9
  TOP w0.16: v1(67.65,11.35) 67.65,12.9 67.83,13.08 67.83,13.75 66.87,14.72 66.87,19.37 R658.2 ; R695.1 v1(78.45,11.72)
  BOTTOM w0.16: v1(78.45,11.72) 77.62,12.55 68.85,12.55 v1(67.65,11.35)
PTE8_MCU: length 11.4
  TOP w0.16: U37.9 71.74,26.49 71.28,26.03 U36.13 71.28,23.81 70.62,23.15 69.64,23.15 R658.1 68.08,20.54 68.08,19.49 67.55,18.96 R655.1
PTE9: length 111.8
  TOP w0.16: U36.12 69.21,26.19 67.5,24.49 67.5,21.76 66.53,20.79 66.53,14.31 v1(66.19,13.97)
  L3_INT_1 w0.165: v1(52.49,8.13) 52.49,12.03 51.89,12.62 51.89,19.05 50.13,20.82 50.13,24.4 49.66,24.86 49.66,34.44 49.53,34.58 49.53,34.72 47.5,36.75 47.5,42.26 38.76,51 36.19,51 35.08,52.12 33.4,52.12 32.82,52.7 32.82,54.53 33.27,54.99 v1(38.5,54.99)
  BOTTOM w0.16: v1(66.19,13.97) 65.59,13.37 58.35,13.37 55.17,10.19 53.45,10.19 52.49,9.23 v1(52.49,8.13) ; v1(38.5,54.99) 52.47,54.99 54.09,53.38 J1.8
RESET_S32K: length 203.7
  TOP w0.127: 71.78,32.14 71.93,31.99 72.42,31.99 72.78,31.63 U37.31
  TOP w0.16: R732.1 14.12,46.86 J104.1 11.71,49.28 R5.2 11.71,51.31 v1(11.2,51.82) ; U1.7 7.71,49.05 7.55,48.89 v1(7.26,48.89) ; R715.1 44.16,6.92 v1(43.97,6.73) ; R4.2 6.06,52.51 v1(6.04,52.51) 6.16,52.64 6.16,54.02 7.09,54.94 TP539.1 ; J14.10 81.1,48.44 80.77,48.77 80.77,49.73 80.55,49.95 R574.2 79.84,50.41 v1(80.06,50.62) ; v1(44.41,26.07) 44.28,25.95 R585.2 ; v1(62.21,45.26) 63.59,46.65 TS7.1 68.69,46.65 69.84,45.5 72.77,45.5 73.22,45.06 73.22,40.4 71.05,38.23 71.05,35.54 71.78,34.81 71.78,33.15 U36.47 71.78,32.14
  L3_INT_1 w0.165: v1(43.97,6.73) 43.97,5.97 44.21,5.72 44.21,4.38 44.73,3.87 50.96,3.87 52.28,5.19 52.28,6.28 52.95,6.95 52.95,12.6 52.45,13.11 52.45,18.64 53.45,19.65 53.45,24.65 52.67,25.44 52.67,26.96 v1(53,27.29) 52.73,27.56 52.73,38.86 50.9,40.69 v1(50.9,45.29) ; v1(80.06,50.62) 80.67,50.01 v1(80.67,44.96)
  BOTTOM w0.16: v1(44.41,26.07) 44.83,26.5 45.47,26.5 45.74,26.23 45.74,26.21 45.77,26.19 49.59,26.19 50.69,27.29 v1(53,27.29) ; v1(7.26,48.89) 7.26,49.25 6.06,50.46 6.06,52.51 v1(6.04,52.51) 6.04,54.02 7.01,54.99 9.7,54.99 9.98,54.71 9.98,52.1 10.26,51.82 v1(11.2,51.82) 12.93,50.08 17.47,50.08 18.18,50.8 25.17,50.8 26.44,49.53 27.07,49.53 27.71,50.16 32.92,50.16 36.54,46.55 41.27,46.55 42.53,45.29 v1(50.9,45.29) 50.92,45.26 v1(62.21,45.26) 62.53,45.59 71.12,45.59 72.55,44.16 77.1,44.16 77.87,44.93 80.64,44.93 v1(80.67,44.96)
RGB_BLUE: length 35.3
  TOP w0.16: v1(88.02,8.04) TPAD97.1 R603.1 ; R655.2 67.55,14.74 68.35,13.95 68.35,11.3 67.97,10.92 67.97,8 v1(69.11,6.86)
  BOTTOM w0.16: v1(88.02,8.04) 85.02,8.04 83.84,6.86 v1(69.11,6.86)
RGB_GREEN: length 50.9
  TOP w0.16: R601.1 TPAD95.1 v1(90.28,5.5) ; R654.2 v1(61.33,23.74)
  L3_INT_1 w0.165: v1(90.28,5.5) 90.28,7 87.59,9.69 v1(87.59,24.8)
  BOTTOM w0.16: v1(61.33,23.74) 68.87,23.74 70.4,25.26 84.09,25.26 85.17,24.18 86.97,24.18 v1(87.59,24.8)
RGB_RED: length 52.1
  TOP w0.16: R598.1 TPAD94.1 v1(90.46,3.21) ; R653.2 v1(61.28,24.88)
  L3_INT_1 w0.165: v1(90.46,3.21) 86.8,6.87 86.8,24.87 v1(86.53,25.14)
  BOTTOM w0.16: v1(61.28,24.88) 69.2,24.88 69.94,25.62 86.06,25.62 v1(86.53,25.14)
SBC_CAN_RX: length 22.7
  TOP w0.16: v1(58.95,33.95) 58.95,32.34 R649.2 ; R588.2 50.89,26.07 v1(50.88,26.07)
  L3_INT_1 w0.165: v1(50.88,26.07) 52.35,27.54 52.35,34.24 51.12,35.47 v1(51.12,35.83)
  BOTTOM w0.16: v1(51.12,35.83) 53,33.95 58.94,33.95 58.95,33.96 v1(58.95,33.95)
SBC_CAN_RX_LS: length 35.3
  TOP w0.16: U19.7 21.2,18.74 21.31,18.85 v1(21.69,18.85) ; v1(50.13,17.56) 50.51,17.95 TP512.1 R580.1
  BOTTOM w0.16: v1(50.13,17.56) 50.13,18.41 49.49,19.04 47.19,19.04 46.35,18.2 43.5,18.2 42.48,17.18 37.27,17.18 35.45,19 21.84,19 v1(21.69,18.85)
SBC_CAN_TX: length 26.5
  TOP w0.16: R650.2 59.55,33.95 v1(60.64,35.04) ; R587.2 49.87,25.82 v1(50.13,26.07)
  L3_INT_1 w0.165: v1(50.25,35.98) 50.25,35.47 51.97,33.76 51.97,27.91 v1(50.13,26.07)
  BOTTOM w0.16: v1(50.25,35.98) 50.58,36.31 51.71,36.31 53.67,34.34 58.49,34.34 59.19,35.04 v1(60.64,35.04)
SBC_CAN_TX_LS: length 33.5
  TOP w0.16: v1(21.17,15.53) 20.46,16.24 U19.2 ; v1(48.86,18.58) 48.35,19.09 TP513.1 49.42,19.65 R579.1
  BOTTOM w0.16: v1(21.17,15.53) 21.5,15.86 47.05,15.86 48.86,17.67 v1(48.86,18.58)
SBC_CS: length 31.3
  TOP w0.16: v1(68.8,16.04) 68.69,16.14 R635.1 ; R592.2 v1(41.24,19.85)
  BOTTOM w0.16: v1(41.24,19.85) 51.17,19.85 51.61,19.41 56.09,19.41 59.2,16.3 62.45,16.3 62.52,16.37 68.47,16.37 v1(68.8,16.04)
SBC_CS_LS: length 30.7
  TOP w0.16: R584.1 40.03,16.04 40.16,16.17 TP517.1 v1(40.86,15.02) ; v1(14.95,15.53) 15.84,15.53 16.05,15.74 U19.20
  BOTTOM w0.16: v1(40.86,15.02) 40.56,14.73 15.75,14.73 v1(14.95,15.53)
SBC_LIMP: length 57.3
  TOP w0.16: R668.1 74.92,41.54 v1(74.89,41.57) ; U32.6 44.68,23.68 45.27,24.26 R609.2 45.3,25.25 45.3,26.03 45.28,26.05 v1(45.28,26.03)
  L3_INT_1 w0.165: v1(74.6,23.47) 76.14,25.01 76.14,40.32 v1(74.89,41.57)
  BOTTOM w0.16: v1(74.6,23.47) 73.23,24.83 71.14,24.83 69.58,23.28 57.75,23.28 54.24,26.78 52.31,26.78 51.13,25.61 45.73,25.61 45.28,26.05 v1(45.28,26.03)
SBC_LIMP_LS: length 38.5
  TOP w0.16: R536.2 15.01,20.6 15.24,20.82 v1(16.58,20.82) U19.11 ; R578.1 44.95,19.62 46.04,19.62 TP505.1 v1(46.06,18.78)
  BOTTOM w0.16: v1(46.06,18.78) 37.99,18.78 37.42,19.35 37.42,19.75 36.67,20.51 36.67,20.87 36.16,21.37 34.93,21.37 34.67,21.63 33.65,21.63 32.55,20.54 23.91,20.54 22.73,21.72 22.14,21.72 22.14,21.72 20.32,21.72 19.42,20.82 v1(16.58,20.82)
SBC_MISO: length 44.5
  TOP w0.16: R637.1 v1(77.46,16.76) ; v1(37.43,20.61) R591.2
  BOTTOM w0.16: v1(77.46,16.76) 76.22,16.76 75.04,15.58 68.01,15.58 67.6,15.99 62.78,15.99 62.75,15.96 59.06,15.96 55.95,19.07 51.35,19.07 51.04,19.38 39.56,19.38 39.51,19.34 38.13,19.34 37.77,19.7 37.77,20.27 v1(37.43,20.61)
SBC_MISO_LS: length 22.8
  TOP w0.16: v1(20.98,20.45) 20.98,20.06 20.66,19.74 U19.9 ; v1(35.27,16.93) 35.78,16.42 TP516.1 38.06,16.42 R583.1
  BOTTOM w0.16: v1(20.98,20.45) 20.5,19.96 20.5,18.39 21.95,16.93 v1(35.27,16.93)
SBC_MOSI: length 70.2
  TOP w0.16: R636.1 v1(69.84,16.57) ; v1(32.22,29.38) 32.85,29.38 34.04,28.19 37.98,28.19 38.13,28.04 39.4,28.04 R590.2
  L3_INT_1 w0.165: v1(32.22,29.38) 32.22,32.3 36.28,36.36 v1(38.32,36.36) ; v1(70.48,32.28) 70.48,17.21 v1(69.84,16.57)
  BOTTOM w0.16: v1(38.32,36.36) 38.7,36.74 41.22,36.74 42.7,35.26 50.97,35.26 52.76,33.47 61.39,33.47 61.86,33 69.75,33 v1(70.48,32.28)
SBC_MOSI_LS: length 28.3
  TOP w0.16: TP515.1 21.29,16.42 v1(21.17,16.54) 21.09,16.62 20.6,16.62 20.48,16.74 U19.3 ; v1(33.74,20.99) 33.91,21.16 36.35,21.16 36.9,21.72 36.9,21.92 37.81,22.82 R582.1
  BOTTOM w0.16: v1(33.74,20.99) 34.2,20.53 34.2,19.79 33.93,19.52 23.26,19.52 21.82,20.95 20.72,20.95 20.1,20.33 20.1,17.13 20.68,16.54 v1(21.17,16.54)
SBC_RST_LS: length 29.6
  TOP w0.16: v1(43.65,17.44) 43.9,17.69 TP506.1 R577.1 ; R594.2 21.5,19.93 v1(21.12,19.54) 20.82,19.24 U19.8
  BOTTOM w0.16: v1(43.65,17.44) 43.05,16.84 37.13,16.84 35.31,18.66 22.87,18.66 22.43,18.22 21.35,18.22 21.12,18.45 v1(21.12,19.54)
SBC_SCK: length 80.4
  TOP w0.16: v1(32.73,28.49) 33.24,28.49 33.87,27.85 37.84,27.85 37.99,27.7 38.72,27.7 R589.2 ; R638.1 v1(78.6,16.76)
  L3_INT_1 w0.165: v1(80.56,33.69) 78.14,31.27 78.14,17.23 v1(78.6,16.76) ; v1(38.19,35.47) 36.79,35.47 33.01,31.69 33.01,28.77 v1(32.73,28.49)
  BOTTOM w0.16: v1(38.19,35.47) 41.9,35.47 43.29,34.07 51.24,34.07 52.18,33.14 61.25,33.14 61.72,32.66 69.16,32.66 70.25,31.58 78.44,31.58 v1(80.56,33.69)
SBC_SCK_LS: length 20.7
  TOP w0.16: R581.1 36.03,22.64 TP514.1 35.22,21.81 v1(35.14,21.88) ; U19.10 19.88,20.62 20.22,20.95 20.22,22.17 v1(20.2,22.17)
  BOTTOM w0.16: v1(35.14,21.88) 35.05,21.97 24.08,21.97 22.77,23.28 20.46,23.28 20.22,23.04 20.22,22.17 v1(20.2,22.17)
SDA_EXTAL: length 5.4
  TOP w0.16: Y1.3 21.74,33.58 21.3,33.58 C23.1 20.55,34.32 20.55,36.2 U8.17
SDA_JTAG_TCLK: length 12.2
  TOP w0.16: U8.12 15.91,36.45 14.63,36.45 13.83,35.65 13.83,30.86 14.57,30.13 J12.4
SDA_JTAG_TDI: length 8
  TOP w0.16: U8.13 v1(17.23,37.07)
  BOTTOM w0.16: v1(17.23,37.07) 14.54,34.38 14.54,32.82 14.69,32.67 J12.8
SDA_JTAG_TDO: length 10.5
  TOP w0.16: U8.14 17.25,36.38 16.56,36.38 16.25,36.07 15.01,36.07 14.31,35.37 14.31,31.65 14.57,31.4 J12.6
SDA_JTAG_TMS: length 16.4
  TOP w0.16: J12.2 16.05,28.81 17.17,27.69 20.98,27.69 21.23,27.94 21.23,28.96 R77.2 20.47,32.44 19.23,33.68 19.23,34.77 18.31,35.69 18.31,36.73 U8.15
SDA_LED: length 2.8
  TOP w0.16: D2.C 22.87,42.45 21.91,42.45 21.04,41.58
SDA_LED_R: length 1.2
  TOP w0.16: R12.2 D2.A
SDA_RST: length 18.5
  TOP w0.16: v1(26.69,34.76) 26.69,34.76 25.69,35.76 25.69,35.76 R57.2 24.86,36.59 24.86,36.59 TP12.1 21.16,37.01 U8.19
  BOTTOM w0.16: v1(26.69,34.76) 16.24,34.76 16.05,34.56 J12.10
SDA_RST_LED: length 7.6
  TOP w0.16: Q11.6 6.51,47.13 v1(6.17,47.47) ; v1(4.85,52.45) 5.23,52.45 5.5,52.72 D1.C
  BOTTOM w0.16: v1(4.85,52.45) 4.85,48.79 v1(6.17,47.47)
SDA_RST_TGTMCU_B: length 14.5
  TOP w0.16: R701.1 v1(20.34,46.23) ; v1(24.18,38.33) 23.62,37.76 21.83,37.76 U8.21
  BOTTOM w0.16: v1(20.34,46.23) 20.72,46.23 22.42,44.54 22.42,38.97 23.06,38.33 v1(24.18,38.33)
SDA_RST_TGTMCU_J_B: length 18.2
  TOP w0.16: U1.2 8.11,51.65 8.28,51.82 8.81,51.82 9.25,52.26 9.25,52.81 9.52,53.09 R3.2 10.87,53.09 12.72,51.23 R5.1 13.31,50.16 14.37,49.1 14.37,47.71 14.97,47.11 16.91,47.11 J104.3 20.34,48.13
SDA_RX_EN: length 3.7
  TOP w0.16: v1(32.98,44.62) 32.8,44.43 R16.1 32.02,44.44 R15.2 U4.5
SDA_SPI0_CS: length 9.7
  TOP w0.16: R38.2 TP7.1 25.78,40.15 25.67,40.04 24.23,40.04 22.69,38.5 22.5,38.5 U8.23
SDA_SPI0_RST_B: length 10.2
  TOP w0.16: U8.22 22.17,38.13 23.17,38.13 24.2,39.15 TP8.1 25.93,39.15 26.34,39.55 30.08,39.55 30.48,39.15 R41.2
SDA_SPI0_SCK: length 9.5
  TOP w0.16: U8.26 22.63,41.05 v1(25.08,41.05) ; U10.3 28.48,37.62 28.04,37.19 27.59,37.19 v1(27.49,37.09)
  BOTTOM w0.16: v1(25.08,41.05) 25.08,40.04 27.49,37.63 v1(27.49,37.09)
SDA_SPI0_SIN: length 11.4
  TOP w0.16: U8.28 22.12,41.95 23.59,41.95 26.22,44.58 27.09,44.58 27.41,44.89 27.41,46.15 27.37,46.19 27.37,46.19 27.08,46.48 27.08,47.38 27.2,47.5 U2.3
SDA_SPI0_SOUT: length 7.5
  TOP w0.16: U8.27 22.44,41.56 v1(23.99,41.56) 26.4,41.56 27.3,40.66 U7.3
SDA_SWD_EN: length 2.5
  TOP w0.16: R41.1 R47.1 33.88,39.15 34.03,39.3 U9.6
SDA_SWD_EN_B: length 19.3
  TOP w0.16: U8.16 v1(19.63,36.21) ; v1(35.58,38.7) R49.2
  BOTTOM w0.16: v1(35.58,38.7) 35.58,38.23 32.97,35.62 27.7,35.62 27.1,36.21 v1(19.63,36.21)
SDA_SWD_EN_B_R: length 3.1
  TOP w0.16: U9.1 35.63,39.3 35.78,39.15 R42.2 36.6,39.13 37.17,38.55 37.17,38.54 v1(37.17,38.54) 37.17,38.52 R49.1
SDA_SWD_EN_R: length 3.7
  TOP w0.16: U10.5 R52.2 31.03,38.13 R51.1 32.03,38.13 R47.2
SDA_SWD_OE: length 2.5
  TOP w0.16: R38.1 R35.1 33.84,40.15 33.99,40 U9.4
SDA_SWD_OE_B: length 19.5
  TOP w0.16: v1(25.27,37.82) 24.3,37.82 23.87,37.39 21.49,37.39 21.04,37.84 ; v1(35.85,40.73) 35.59,41 35.59,41.44 R32.2
  BOTTOM w0.16: v1(25.27,37.82) 26.41,36.67 27.28,36.67 27.93,36.03 32.5,36.03 35.12,38.65 35.12,40 v1(35.85,40.73)
SDA_SWD_OE_B_R: length 3.5
  TOP w0.16: v1(36.6,42.23) R32.1 R39.1 35.79,40.15 35.64,40 U9.3
SDA_SWD_OE_R: length 3.7
  TOP w0.16: R35.2 31.99,41.16 R31.1 R30.2 30.43,41.19 30.4,41.16 U7.5
SDA_USB_CONN_DN: length 13.5
  TOP w0.145: R25.1 15.73,43.97 15.5,44.2 13.11,44.2 12.43,43.52 8.1,43.52 7.94,43.36 D19.2 7.93,42.94 7.63,42.94 7.48,43.08 7.48,43.39 7.34,43.53 4.81,43.53 4.65,43.37 J7.2
SDA_USB_CONN_DP: length 13.9
  TOP w0.145: R21.1 15.94,44.18 15.62,44.49 12.98,44.49 12.31,43.82 8.11,43.82 7.92,44.01 D18.2 7.73,44.46 7.57,44.3 7.57,43.99 7.41,43.83 4.86,43.83 4.67,44.02 J7.3
SDA_USB_DN: length 2.1
  TOP w0.145: U8.4 17.65,41.94 17.65,42.08 17.08,42.65 R25.2
SDA_USB_DP: length 2.1
  TOP w0.145: R21.2 17.25,42.9 17.29,42.86 17.29,42.86 17.84,42.31 17.99,42.31 U8.3
SDA_USB_P5V_SENSE: length 4.6
  TOP w0.16: U8.30 21.47,42.72 R20.1 22.79,44.04 22.79,44.04 R14.2 v1(23.98,45.22)
SDA_USBSHIELD: length 11.1
  TOP w0.508: J7.6 3.36,46.25 1.45,44.34 J7.8 1.45,43.74 3.4,41.8 J7.7 5.47,41.8 6.21,41.06 L2.1
SDA_VOUT33: length 5.9
  TOP w0.254: C9.1 15.71,41.97 16.91,41.97 U8.5
  TOP w0.508: C9.1 15.18,41.44 13.8,41.44 13.55,41.69 R627.1
SDA_XTAL: length 5.3
  TOP w0.16: 24.28,34.43 23.41,35.3 23.41,35.71 C20.1 22.61,36.51 20.95,36.51 U8.18
SW1_RST_B: length 17
  TOP w0.16: SW5.4 SW5.2 25.12,51.06 24.41,50.36 C1.1 17.15,49.89 J104.2
SWD_CLK_TGTMCU_BUF: length 1.5
  TOP w0.16: U10.4 29.34,37.23 29.55,37.01 R626.2
SWD_DIO_TGTMCU_BUF: length 10.4
  TOP w0.16: U2.6 v1(32.35,47.5) 32.35,47.5 R625.2 ; U7.4 v1(30.02,40.66)
  BOTTOM w0.16: v1(30.02,40.66) 31.93,42.57 31.93,47.09 v1(32.35,47.5)
TC_EXTAL_TP: length 2.1
  TOP w0.16: U8.10 16.39,38.34 16.17,38.34 15.72,37.89 TP11.1
TC_SDA_USB_ID_TP: length 1.6
  TOP w0.16: TP6.1 J7.4
TC_XTAL_TP: length 3
  TOP w0.16: U8.9 16.19,38.85 15.83,38.85 TP10.1
TOUCH_PTA7: length 22.5
  TOP w0.16: v1(86.13,26.67) 86.13,26.16 R747.1 ; v1(85.43,11.19) R527.2 R528.2
  BOTTOM w0.16: v1(85.43,11.19) 84.61,12.01 84.61,17.02 88.16,20.57 88.16,25.17 86.66,26.67 v1(86.13,26.67)
TOUCH_PTC1: length 12.8
  TOP w0.16: R525.2 86.51,32.86 86.51,32.86 R172.2 86.51,34.57 85.95,35.13 85.95,37.95 v1(86.64,38.63) ; R740.2 81.66,39.04 v1(83.26,39.04)
  BOTTOM w0.16: v1(83.26,39.04) 83.67,38.63 v1(86.64,38.63)
TOUCH_PTC15: length 3.3
  TOP w0.16: C535.1 R746.2 R528.1
TOUCH_PTC16: length 3.3
  TOP w0.16: R525.1 R744.2 C533.1
TP_2102_A: length 2.5
  TOP w0.16: U1.3 R607.2 7.71,53.43 v1(7.74,53.46)
TP_2102_B: length 1.5
  TOP w0.16: U1.6 5.94,49.68 R608.2
UART1_RX_TGTMCU_BUF: length 7.3
  TOP w0.16: U4.4 30.29,43.94 30.44,43.8 32.66,43.8 v1(32.98,43.47) 33.08,43.57 35.81,43.57 35.97,43.41 R24.1
UART1_RX_TGTMCU_R: length 8.8
  TOP w0.16: v1(25.86,40.9) 25.39,40.42 23.84,40.42 23.67,40.6 22.89,40.6 U8.25 ; U4.3 28.04,43.94 27.83,43.73 v1(27.02,43.73)
  BOTTOM w0.16: v1(25.86,40.9) 25.86,42.07 27.02,43.23 v1(27.02,43.73)
UART1_TX_TGTMCU_BUF: length 8.6
  TOP w0.16: U2.7 32.63,48 32.9,48.28 35.19,48.28 35.58,47.88 35.58,44.81 R18.1
UART1_TX_TGTMCU_R: length 12.1
  TOP w0.16: U8.24 v1(23.29,40.08) ; U2.2 28.24,48.01 27.11,48.01 26.74,47.64 26.74,46.34 27.03,46.05 27.03,45.17 v1(26.95,45.09)
  BOTTOM w0.16: v1(26.95,45.09) 26.5,44.64 26.5,43.3 v1(23.29,40.08)
UART_RX: length 75.4
  TOP w0.16: v1(85.27,23.72) 84.48,24.5 83.96,24.5 R666.1 ; R24.2 v1(34.07,43.05)
  L3_INT_1 w0.165: v1(85.27,23.72) 85.27,25.04 87.27,27.05 87.27,33.86 86.53,34.6 86.53,36.14 v1(86.68,36.28)
  BOTTOM w0.16: v1(86.68,36.28) 85.16,37.8 82.98,37.8 82.12,38.66 79.04,38.66 78.18,37.8 54.34,37.8 53.78,37.24 52.09,37.24 49.58,39.75 44.83,39.75 39.59,45 36.02,45 v1(34.07,43.05)
UART_TX: length 73.3
  TOP w0.16: R18.2 v1(36.98,44.16) ; R667.1 v1(86.32,21.76)
  L3_INT_1 w0.165: v1(86.32,21.76) 86,22.08 86,25.27 87.78,27.05 87.78,34.27 v1(87.11,34.94)
  BOTTOM w0.16: v1(87.11,34.94) 86.8,35.24 65.87,35.24 63.7,37.42 54.5,37.42 53.99,36.91 53.93,36.91 53.92,36.9 51.95,36.9 51.95,36.91 51.94,36.91 49.6,39.24 44.83,39.24 39.51,44.56 37.39,44.56 v1(36.98,44.16)
V_TGTMCU: length 15.9
  TOP w0.203: 3.39,50.47 C2.1 ; C2.1 3.9,50.98 ; C2.1 2.88,50.98 ; 5.48,50.42 5.48,50.93 4.98,50.93 ; 7.11,48.13 C4.1 8.1,48.62 8.1,48.94 8.11,48.95 U1.8
  TOP w0.254: v1(30.04,41.89) 29.81,41.66 U7.6 ; v1(30.05,38.7) 29.88,38.7 29.8,38.62 U10.6 ; U4.6 v1(29.34,46.01) ; v1(30,48.01) 30.49,48.5 U2.8 ; C8.1 v1(30.09,42.77)
  TOP w0.889: v1(39.52,43.59) v1(39.52,42.57) 39.69,42.4 39.69,40.33 38.85,39.49 SH1.1
  vias: v1(6.88,48.11)
VSUP: length 29.1
  TOP w0.254: U19.14 v1(15.66,18.74)
  TOP w0.508: TP508.1 34.89,15.6 ; TP508.1 35.46,15.02 ; TP508.1 34.31,15.02 ; TP508.1 34.89,14.45 ; 36.16,18.07 C546.1 35.73,18.16 ; J108.2 19.54,24.17 C552.1 ; C128.1 39.08,11.98 ; C128.1 37.11,12.99 ; C128.1 37.11,10.96 ; C128.1 35.14,11.98 ; 34.51,18.58 C47.1 35.01,18.07
  TOP w0.635: 32.08,16.87 Q1.2 ; Q1.2 32.88,17.37 ; Q1.2 32.08,17.86 ; U21.7 21.3,24.16 21.3,24.17 C552.1 ; 32.26,11.98 D9.C ; D9.C 33.15,10.73 ; D9.C 33.15,13.22 ; D9.C 34.04,11.98 ; v1(11.06,9.95) 11.06,9.67 10.42,9.04 R537.1 ; 32.08,15.6 Q1.1 ; Q1.1 32.08,16.59 ; Q1.1 32.88,16.1 ; 32.08,18.14 Q1.3 32.88,18.64
  BOTTOM w0.203: 18.31,24.45 J108.2 17.36,25.4
  vias: v1(32.09,13.88) v1(33.49,13.88) v1(34.57,12.57) v1(34.63,13.88) v1(35.57,13.88)
VTRG_EN: length 4.6
  TOP w0.16: U11.3 v1(9.98,31.94) R70.2 R68.1 R69.2
VTRG_FAULT_B: length 16.3
  TOP w0.16: U11.4 11.22,35.53 R60.2 v1(12.67,35.53) ; U8.32 20.38,43.04 v1(20.38,43.64)
  BOTTOM w0.16: v1(20.38,43.64) 20.38,43.18 17.59,40.39 15.71,40.39 14.62,39.3 14.62,37.48 v1(12.67,35.53)
